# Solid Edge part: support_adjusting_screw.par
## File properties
Title: Support adjusting screw
Author: vicky raina
Template: Normal.par
Last saved by: Robert a Rhodes jr
Revision: 6
Application: Solid Edge
Material: aluminum
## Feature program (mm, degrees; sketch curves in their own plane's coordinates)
sketch for "unnamed Protrusion 1" plane through (0, 0, 0) normal (0, -1, 0) x-axis (1, 0, 0)
  circle centre (0, 0) radius 38.1
extrude "unnamed Protrusion 1" add finite 584.2 along +normal
sketch for "unnamed Cutout 1" plane through (0, -521.208, 0) normal (0, -1, 0) x-axis (1, 0, 0)
extrude "unnamed Cutout 1" cut finite 76.2 along +normal
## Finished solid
Body 1: solid body, 5 faces, 4 edges, 0 vertices.
  Faces by surface: plane 3, cylinder 2
  Edges by curve: circle 4
Bounding box of the edges (mm): 76.200 x 584.200 x 76.200, from (-38.1, -584.2, -38.1) to (38.1, 0, 38.1).
Cylindrical faces by radius (mm): R25.4 x1, R38.1 x1
Planar faces by outward normal: +y 1, -y 2
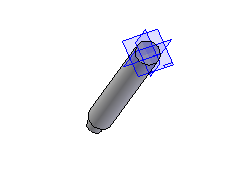
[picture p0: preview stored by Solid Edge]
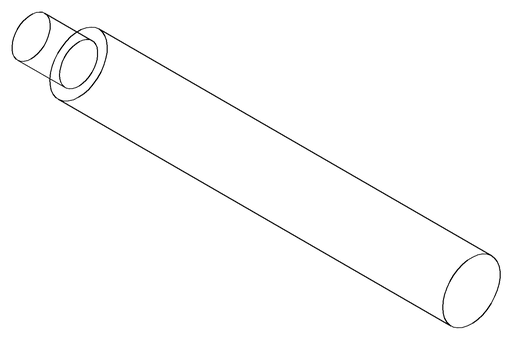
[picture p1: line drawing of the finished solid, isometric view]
